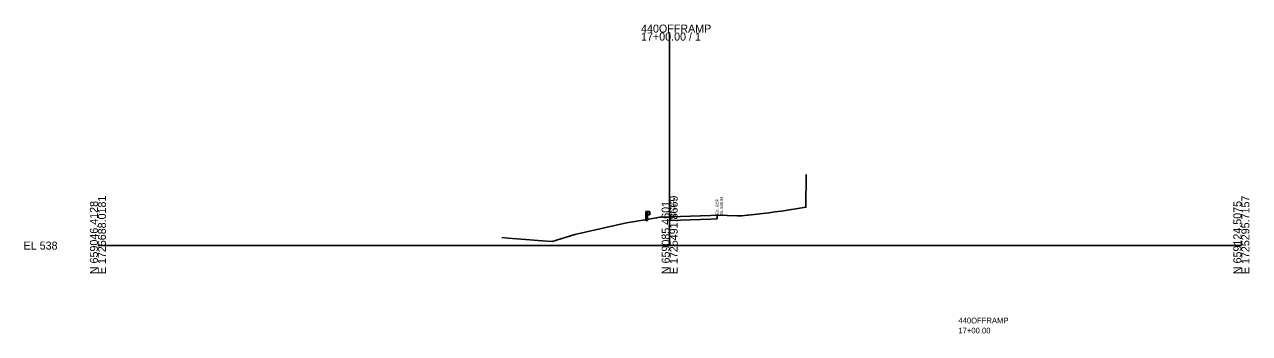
# Model space of a CAD drawing. Extents: x 1728898 to 1729326, y 661368 to 668397.
# Drawn here: x 1728897.8 to 1729326.3, y 663847.3 to 663955.5 of the extents above; entities that cross this region are included whole.
import ezdxf

# ---------------------------------------------------------------- set-up
doc = ezdxf.new("R2010")
doc.units = 0
for name, color, linetype in [('DESIGN - SHEET - Light Grid', 7, 'Continuous'), ('DESIGN - TYPICAL - Guardrail', 7, 'Continuous'), ('DESIGN - TYPICAL - Warning Text', 7, 'Continuous'), ('SURVEY - GROUND - Existing Pavement Layer', 7, 'Continuous'), ('SURVEY - GROUND - Existing Pavement Text', 7, 'Continuous'), ('SURVEY - GROUND - Top of Ground', 7, 'Continuous')]:
    doc.layers.add(name, color=color, linetype=linetype)

msp = doc.modelspace()

# ---------------------------------------------------------------- linework, layer by layer
at = {"layer": 'DESIGN - SHEET - Light Grid'}
for p, q in [((1729123.44, 663878.11), (1729123.44, 663952.66)), ((1728923.44, 663878.11), (1729123.44, 663878.11)), ((1729123.44, 663878.11), (1729323.44, 663878.11))]:
    msp.add_line(p, q, dxfattribs=at)
at = {"layer": 'DESIGN - TYPICAL - Guardrail'}
for p, q in [((1729115.05, 663890.01), (1729115.05, 663887.35)), ((1729115.72, 663890.01), (1729115.05, 663890.01)), ((1729115.05, 663886.79), (1729115.05, 663887.35)), ((1729115.72, 663890.01), (1729116.34, 663890.01)), ((1729115.72, 663887.35), (1729115.72, 663890.01)), ((1729116.34, 663888.84), (1729115.72, 663888.84)), ((1729115.72, 663887.35), (1729115.72, 663886.89)), ((1729116.34, 663890.01), (1729116.34, 663888.84)), ((1729116.34, 663889.93), (1729116.42, 663889.88)), ((1729116.37, 663889.52), (1729116.34, 663889.46)), ((1729116.34, 663889.46), (1729116.34, 663889.42)), ((1729116.34, 663889.42), (1729116.34, 663889.38)), ((1729116.34, 663889.38), (1729116.37, 663889.32)), ((1729116.42, 663888.96), (1729116.34, 663888.91)), ((1729116.58, 663889.64), (1729116.37, 663889.52)), ((1729116.37, 663889.32), (1729116.58, 663889.21)), ((1729116.42, 663889.88), (1729116.58, 663889.76)), ((1729116.58, 663889.09), (1729116.42, 663888.96)), ((1729116.58, 663889.76), (1729116.61, 663889.7)), ((1729116.61, 663889.7), (1729116.58, 663889.64)), ((1729116.58, 663889.21), (1729116.61, 663889.15)), ((1729116.61, 663889.15), (1729116.58, 663889.09)), ((1729115.3, 663886.89), (1729115.05, 663886.79)), ((1729115.55, 663886.85), (1729115.3, 663886.89)), ((1729115.72, 663886.89), (1729115.55, 663886.85))]:
    msp.add_line(p, q, dxfattribs=at)
at = {"layer": 'SURVEY - GROUND - Existing Pavement Layer'}
for p, q in [((1729123.71, 663886.92), (1729123.71, 663888.17)), ((1729123.71, 663886.92), (1729137.76, 663887.41)), ((1729137.76, 663887.41), (1729140.08, 663887.5)), ((1729140.08, 663888.75), (1729140.08, 663887.5))]:
    msp.add_line(p, q, dxfattribs=at)
at = {"layer": 'SURVEY - GROUND - Top of Ground'}
msp.add_lwpolyline([(1729064.71, 663880.92), (1729066.9, 663880.75), (1729071.44, 663880.38), (1729079, 663879.76), (1729082.36, 663879.49), (1729086.93, 663880.92), (1729090.25, 663881.95), (1729108.33, 663886.02), (1729111.93, 663886.64), (1729118.85, 663887.82), (1729120.06, 663888.03), (1729120.6, 663888.05), (1729123.71, 663888.17), (1729137.76, 663888.66), (1729140.08, 663888.75), (1729147.05, 663888.54), (1729148.71, 663888.49), (1729150.54, 663888.74), (1729150.94, 663888.79), (1729158.09, 663889.63), (1729160.23, 663889.88), (1729162.59, 663890.21), (1729171.1, 663891.51), (1729171.25, 663902.96)], dxfattribs=at)

# ---------------------------------------------------------------- texts
at = {"layer": 'DESIGN - SHEET - Light Grid'}
for s, p in [('440OFFRAMP', (1729113.44, 663952.66)), ('17+00.00 / 1', (1729113.44, 663949.86)), ('EL 538', (1728897.44, 663876.71))]:
    msp.add_text(s, height=2.8, dxfattribs=at).set_placement(p)
for s, p in [('N 659046.4128', (1728923.44, 663868.11)), ('E 1725688.0181', (1728926.24, 663868.11)), ('N 659085.4601', (1729123.44, 663868.11)), ('E 1725491.8669', (1729126.24, 663868.11)), ('N 659124.5075', (1729323.44, 663868.11)), ('E 1725295.7157', (1729326.24, 663868.11))]:
    msp.add_text(s, height=2.8, rotation=90, dxfattribs=at).set_placement(p)
at = {"layer": 'DESIGN - TYPICAL - Warning Text'}
for s, p in [('440OFFRAMP', (1729224.44, 663850.86)), ('17+00.00', (1729224.44, 663847.36))]:
    msp.add_text(s, height=2, dxfattribs=at).set_placement(p)
at = {"layer": 'SURVEY - GROUND - Existing Pavement Text'}
for s, p in [('EX. EOP', (1729124.21, 663888.37)), ('EL.548.07', (1729125.71, 663888.37)), ('EX. EOP', (1729140.58, 663888.95)), ('EL.548.64', (1729142.08, 663888.95))]:
    msp.add_text(s, height=1, rotation=90, dxfattribs=at).set_placement(p)

doc.saveas('drawing.dxf')
